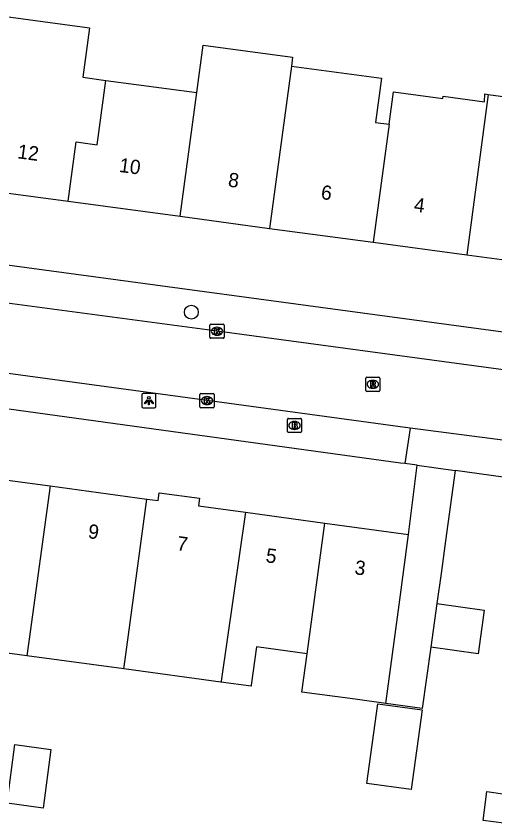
# Model space of a CAD drawing. Extents: x 161258 to 161838, y 380836 to 381727.
# Drawn here: x 161670.2 to 161703.9, y 381549.8 to 381606.5 of the extents above; entities that cross this region are included whole.
import ezdxf

# ---------------------------------------------------------------- set-up
doc = ezdxf.new("R2010")
doc.units = 0
for name, color, linetype in [('IMGEO_Boom', 7, 'Continuous'), ('IMGEO_Brandkraan', 7, 'Continuous'), ('IMGEO_Kolk', 7, 'Continuous'), ('IMGEO_Lichtpunt', 7, 'Continuous'), ('IMGEO_Pand', 7, 'Continuous'), ('IMGEO_Pand_nummerreeks', 7, 'Continuous'), ('IMGEO_Rijbaan_lokaal_open', 7, 'Continuous'), ('IMGEO_Rioolput', 7, 'Continuous'), ('IMGEO_Voetpad_open', 7, 'Continuous')]:
    doc.layers.add(name, color=color, linetype=linetype)

msp = doc.modelspace()

# ---------------------------------------------------------------- linework, layer by layer
at = {"layer": 'IMGEO_Boom'}
msp.add_circle((161682.565, 381585.699), 0.489, dxfattribs=at)
at = {"layer": 'IMGEO_Brandkraan'}
for p, q in [((161689.314, 381577.311), (161689.314, 381578.163)), ((161689.389, 381578.237), (161690.241, 381578.237)), ((161690.315, 381578.163), (161690.315, 381577.311)), ((161689.825, 381577.457), (161689.8, 381577.457)), ((161689.802, 381578.017), (161689.827, 381578.017)), ((161690.241, 381577.237), (161689.389, 381577.237))]:
    msp.add_line(p, q, dxfattribs=at)
for points in [[(161689.314, 381577.311), (161689.314, 381578.163)], [(161689.389, 381578.237), (161690.241, 381578.237)], [(161690.315, 381578.163), (161690.315, 381577.311)], [(161689.662, 381577.937), (161689.662, 381577.537), (161689.875, 381577.537)], [(161689.893, 381577.937), (161689.662, 381577.937)], [(161689.841, 381577.856), (161689.787, 381577.856), (161689.787, 381577.78)], [(161689.787, 381577.78), (161689.84, 381577.78)], [(161689.849, 381577.704), (161689.787, 381577.704), (161689.787, 381577.623)], [(161689.787, 381577.623), (161689.849, 381577.623)], [(161690.241, 381577.237), (161689.389, 381577.237)]]:
    msp.add_lwpolyline(points, dxfattribs=at)
for centre, radius, start, end in [((161689.391, 381578.161), 0.0765, 91.552, 178.448), ((161689.391, 381578.161), 0.0765, 91.552, 178.448), ((161690.239, 381578.161), 0.0765, 1.552, 88.448), ((161690.239, 381578.161), 0.0765, 1.552, 88.448), ((161689.842, 381577.818), 0.0379, 267.8285, 90.9355), ((161689.85, 381577.663), 0.0404, 269.8759, 90.5077), ((161689.881, 381577.788), 0.251, 268.6676, 293.5347), ((161689.897, 381577.792), 0.145, 59.4692, 91.5367), ((161689.922, 381577.839), 0.0922, 285.5137, 58.1501), ((161689.927, 381577.647), 0.105, 301.3115, 78.989), ((161689.391, 381577.313), 0.0765, 181.552, 268.448), ((161689.391, 381577.313), 0.0765, 181.552, 268.448), ((161690.239, 381577.313), 0.0765, 271.552, 358.448), ((161690.239, 381577.313), 0.0765, 271.552, 358.448)]:
    msp.add_arc(centre, radius, start, end, dxfattribs=at)
for centre, major_axis, ratio, start_param, end_param in [((161689.801, 381577.737), (-0.387, 0.002), 0.722429, 4.712389, 7.853982), ((161689.826, 381577.737), (-0.39, 0.002), 0.717154, 1.570796, 4.712389)]:
    msp.add_ellipse(centre, major_axis=major_axis, ratio=ratio, start_param=start_param, end_param=end_param, dxfattribs=at)
at = {"layer": 'IMGEO_Kolk'}
for p, q in [((161683.942, 381584.859), (161684.794, 381584.859)), ((161683.867, 381583.933), (161683.867, 381584.785)), ((161684.355, 381584.639), (161684.38, 381584.639)), ((161684.868, 381584.785), (161684.868, 381583.933)), ((161684.794, 381583.859), (161683.942, 381583.859)), ((161684.378, 381584.079), (161684.353, 381584.079)), ((161683.164, 381579.056), (161683.164, 381579.908)), ((161683.239, 381579.982), (161684.091, 381579.982)), ((161683.652, 381579.762), (161683.677, 381579.762)), ((161684.165, 381579.908), (161684.165, 381579.056)), ((161683.675, 381579.202), (161683.65, 381579.202)), ((161684.091, 381578.982), (161683.239, 381578.982))]:
    msp.add_line(p, q, dxfattribs=at)
for points in [[(161683.942, 381584.859), (161684.794, 381584.859)], [(161683.867, 381583.933), (161683.867, 381584.785)], [(161684.188, 381584.559), (161684.311, 381584.559), (161684.311, 381584.408), (161684.441, 381584.559), (161684.605, 381584.559), (161684.459, 381584.408), (161684.612, 381584.159), (161684.46, 381584.159), (161684.375, 381584.323), (161684.311, 381584.256), (161684.311, 381584.159), (161684.188, 381584.159), (161684.188, 381584.559)], [(161684.868, 381584.785), (161684.868, 381583.933)], [(161684.794, 381583.859), (161683.942, 381583.859)], [(161683.164, 381579.056), (161683.164, 381579.908)], [(161683.239, 381579.982), (161684.091, 381579.982)], [(161684.165, 381579.908), (161684.165, 381579.056)], [(161683.485, 381579.682), (161683.608, 381579.682), (161683.608, 381579.531), (161683.738, 381579.682), (161683.902, 381579.682), (161683.756, 381579.531), (161683.909, 381579.282), (161683.757, 381579.282), (161683.672, 381579.446), (161683.608, 381579.379), (161683.608, 381579.282), (161683.485, 381579.282), (161683.485, 381579.682)], [(161684.091, 381578.982), (161683.239, 381578.982)]]:
    msp.add_lwpolyline(points, dxfattribs=at)
for centre, start, end in [((161683.944, 381584.783), 91.552, 178.448), ((161683.944, 381584.783), 91.552, 178.448), ((161684.792, 381584.783), 1.552, 88.448), ((161684.792, 381584.783), 1.552, 88.448), ((161683.944, 381583.935), 181.552, 268.448), ((161683.944, 381583.935), 181.552, 268.448), ((161684.792, 381583.935), 271.552, 358.448), ((161684.792, 381583.935), 271.552, 358.448), ((161683.241, 381579.906), 91.552, 178.448), ((161683.241, 381579.906), 91.552, 178.448), ((161684.089, 381579.906), 1.552, 88.448), ((161684.089, 381579.906), 1.552, 88.448), ((161683.241, 381579.058), 181.552, 268.448), ((161683.241, 381579.058), 181.552, 268.448), ((161684.089, 381579.058), 271.552, 358.448), ((161684.089, 381579.058), 271.552, 358.448)]:
    msp.add_arc(centre, 0.0765, start, end, dxfattribs=at)
for centre, major_axis, ratio, start_param, end_param in [((161684.354, 381584.359), (-0.387, 0.002), 0.722429, 4.712389, 7.853982), ((161684.379, 381584.359), (-0.39, 0.002), 0.717154, 1.570796, 4.712389), ((161683.651, 381579.482), (-0.387, 0.002), 0.722429, 4.712389, 7.853982), ((161683.676, 381579.482), (-0.39, 0.002), 0.717154, 1.570796, 4.712389)]:
    msp.add_ellipse(centre, major_axis=major_axis, ratio=ratio, start_param=start_param, end_param=end_param, dxfattribs=at)
at = {"layer": 'IMGEO_Lichtpunt'}
for p, q in [((161679.082, 381579.883), (161679.082, 381579.076)), ((161679.082, 381579.883), (161679.082, 381579.076)), ((161679.984, 381579.978), (161679.176, 381579.978)), ((161679.984, 381579.978), (161679.176, 381579.978)), ((161680.078, 381579.076), (161680.078, 381579.883)), ((161680.078, 381579.076), (161680.078, 381579.883)), ((161679.176, 381578.982), (161679.984, 381578.982)), ((161679.176, 381578.982), (161679.984, 381578.982))]:
    msp.add_line(p, q, dxfattribs=at)
for points in [[(161679.456, 381579.547), (161679.495, 381579.519), (161679.307, 381579.257), (161679.269, 381579.284), (161679.456, 381579.547)], [(161679.558, 381579.499), (161679.605, 381579.499), (161679.605, 381579.177), (161679.558, 381579.177), (161679.558, 381579.499)], [(161679.668, 381579.519), (161679.706, 381579.546), (161679.893, 381579.284), (161679.854, 381579.256), (161679.668, 381579.519)]]:
    msp.add_lwpolyline(points, dxfattribs=at)
msp.add_circle((161679.581, 381579.681), 0.0994, dxfattribs=at)
for centre, start, end in [((161679.176, 381579.883), 90, 180), ((161679.176, 381579.883), 90, 180), ((161679.984, 381579.883), 0, 90), ((161679.984, 381579.883), 0, 90), ((161679.176, 381579.076), 180, 270), ((161679.176, 381579.076), 180, 270), ((161679.984, 381579.076), 270, 0), ((161679.984, 381579.076), 270, 360)]:
    msp.add_arc(centre, 0.0946, start, end, dxfattribs=at)
at = {"layer": 'IMGEO_Pand'}
for points in [[(161668.903, 381603.01), (161669.293, 381605.911), (161669.371, 381606.495), (161675.411, 381605.684), (161674.943, 381602.199), (161676.556, 381601.982)], [(161682.941, 381601.124), (161683.39, 381604.465), (161689.683, 381603.619), (161689.598, 381602.986)], [(161689.598, 381602.986), (161688.066, 381591.586)], [(161689.598, 381602.986), (161695.932, 381602.136), (161695.514, 381599.03), (161696.469, 381598.902)], [(161703.436, 381600.996), (161706.372, 381600.589), (161706.655, 381602.516), (161711.19, 381602.051)], [(161673.908, 381593.488), (161674.468, 381597.658), (161675.948, 381597.459), (161676.556, 381601.982)], [(161676.556, 381601.982), (161682.941, 381601.124)], [(161681.773, 381592.431), (161682.941, 381601.124)], [(161696.469, 381598.902), (161696.775, 381601.179), (161700.243, 381600.713), (161700.264, 381600.871), (161703.168, 381600.481), (161703.187, 381601.031), (161703.436, 381600.996)], [(161703.436, 381600.996), (161701.922, 381589.725)], [(161696.469, 381598.902), (161695.354, 381590.607)], [(161667.735, 381594.317), (161673.908, 381593.488)], [(161673.908, 381593.488), (161681.773, 381592.431)], [(161681.773, 381592.431), (161688.066, 381591.586)], [(161688.066, 381591.586), (161695.354, 381590.607)], [(161701.922, 381589.725), (161707.903, 381588.922), (161708.256, 381591.548), (161709.752, 381591.347)], [(161695.354, 381590.607), (161701.922, 381589.725)], [(161666.71, 381574.256), (161667.111, 381574.202), (161667.779, 381574.711), (161669.169, 381574.522), (161669.65, 381573.891), (161672.64, 381573.485)], [(161672.64, 381573.485), (161671.156, 381562.73), (161671.088, 381562.229), (161670.994, 381561.555)], [(161672.64, 381573.485), (161679.446, 381572.562)], [(161679.446, 381572.562), (161680.224, 381572.456), (161680.298, 381573.003), (161683.135, 381572.618), (161683.063, 381572.087), (161686.368, 381571.638)], [(161677.829, 381560.628), (161677.92, 381561.301), (161679.446, 381572.562)], [(161686.368, 381571.638), (161684.653, 381559.783), (161684.642, 381559.704)], [(161686.368, 381571.638), (161691.942, 381570.882)], [(161690.699, 381561.704), (161691.942, 381570.882)], [(161691.942, 381570.882), (161697.835, 381570.082)], [(161696.223, 381558.208), (161697.162, 381565.128), (161697.835, 381570.082)], [(161699.82, 381565.219), (161703.146, 381564.757), (161702.721, 381561.697), (161699.395, 381562.159)], [(161699.82, 381565.219), (161699.395, 381562.159)], [(161670.994, 381561.555), (161664.925, 381562.378)], [(161690.699, 381561.704), (161687.141, 381562.187), (161686.775, 381559.495), (161686.764, 381559.416), (161684.642, 381559.704)], [(161696.223, 381558.208), (161694.067, 381558.5), (161690.334, 381559.006), (161690.699, 381561.704)], [(161677.829, 381560.628), (161670.994, 381561.555)], [(161684.642, 381559.704), (161677.829, 381560.628)], [(161694.907, 381552.582), (161695.668, 381558.188), (161698.782, 381557.766), (161698.021, 381552.161), (161694.907, 381552.582)], [(161672.15, 381550.861), (161669.619, 381551.2), (161670.169, 381555.312), (161672.7, 381554.974), (161672.15, 381550.861)], [(161703.07, 381549.987), (161703.344, 381552.016), (161706.247, 381551.591), (161705.978, 381549.6), (161703.07, 381549.987)]]:
    msp.add_lwpolyline(points, dxfattribs=at)
at = {"layer": 'IMGEO_Rijbaan_lokaal_open'}
for points in [[(161707.156, 381581.295), (161706.756, 381581.348), (161684.368, 381584.359), (161663.266, 381587.166), (161645.071, 381589.627), (161619.675, 381593.074), (161618.458, 381593.224), (161618.426, 381593.228), (161614.689, 381593.717), (161591.61, 381596.833), (161591.3, 381596.865), (161590.603, 381596.979), (161590.506, 381597.003), (161590.41, 381597.026)], [(161697.936, 381577.548), (161697.62, 381577.589), (161697.6, 381577.592), (161683.665, 381579.482), (161662.594, 381582.337), (161656.447, 381583.147), (161646.629, 381584.448), (161644.429, 381584.771), (161619.122, 381588.157), (161617.916, 381588.319), (161614.153, 381588.812), (161591.008, 381591.931), (161589.798, 381592.101), (161589.764, 381592.108), (161589.729, 381592.114)], [(161704.805, 381576.659), (161697.936, 381577.548)]]:
    msp.add_lwpolyline(points, dxfattribs=at)
at = {"layer": 'IMGEO_Rioolput'}
for p, q in [((161694.819, 381580.202), (161694.819, 381581.054)), ((161694.894, 381581.128), (161695.746, 381581.128)), ((161695.307, 381580.908), (161695.332, 381580.908)), ((161695.82, 381581.054), (161695.82, 381580.202)), ((161695.33, 381580.348), (161695.305, 381580.348)), ((161695.746, 381580.128), (161694.894, 381580.128))]:
    msp.add_line(p, q, dxfattribs=at)
for points in [[(161694.819, 381580.202), (161694.819, 381581.054)], [(161694.894, 381581.128), (161695.746, 381581.128)], [(161695.82, 381581.054), (161695.82, 381580.202)], [(161695.408, 381580.826), (161695.156, 381580.828), (161695.156, 381580.428)], [(161695.156, 381580.428), (161695.28, 381580.428), (161695.28, 381580.59), (161695.291, 381580.59)], [(161695.334, 381580.747), (161695.28, 381580.747), (161695.28, 381580.666)], [(161695.28, 381580.666), (161695.332, 381580.666)], [(161695.338, 381580.561), (161695.409, 381580.428), (161695.549, 381580.428), (161695.484, 381580.554)], [(161695.746, 381580.128), (161694.894, 381580.128)]]:
    msp.add_lwpolyline(points, dxfattribs=at)
for centre, radius, start, end in [((161694.896, 381581.052), 0.0765, 91.552, 178.448), ((161694.896, 381581.052), 0.0765, 91.552, 178.448), ((161695.744, 381581.052), 0.0765, 1.552, 88.448), ((161695.744, 381581.052), 0.0765, 1.552, 88.448), ((161695.29, 381580.537), 0.0533, 26.0293, 88.6989), ((161695.316, 381580.855), 0.19, 274.7715, 282.9687), ((161695.34, 381580.651), 0.0964, 77.0061, 93.1865), ((161695.354, 381580.708), 0.0378, 276.6634, 79.6772), ((161695.407, 381580.716), 0.109, 350.3612, 89.416), ((161695.405, 381580.716), 0.112, 277.5842, 350.9817), ((161695.389, 381580.501), 0.108, 29.5134, 73.7905), ((161694.896, 381580.204), 0.0765, 181.552, 268.448), ((161694.896, 381580.204), 0.0765, 181.552, 268.448), ((161695.744, 381580.204), 0.0765, 271.552, 358.448), ((161695.744, 381580.204), 0.0765, 271.552, 358.448)]:
    msp.add_arc(centre, radius, start, end, dxfattribs=at)
for centre, major_axis, ratio, start_param, end_param in [((161695.306, 381580.628), (-0.387, 0.002), 0.722429, 4.712389, 7.853982), ((161695.331, 381580.628), (-0.39, 0.002), 0.717154, 1.570796, 4.712389)]:
    msp.add_ellipse(centre, major_axis=major_axis, ratio=ratio, start_param=start_param, end_param=end_param, dxfattribs=at)
at = {"layer": 'IMGEO_Voetpad_open'}
for points in [[(161707.511, 381583.893), (161707.085, 381583.95), (161615.118, 381596.359)], [(161697.567, 381575.055), (161697.263, 381575.097), (161654.253, 381581.004), (161654.227, 381580.806)], [(161697.936, 381577.548), (161697.567, 381575.055)], [(161698.43, 381574.937), (161697.567, 381575.055)], [(161697.835, 381570.082), (161698.43, 381574.937)], [(161698.43, 381574.937), (161701.111, 381574.569)], [(161701.111, 381574.569), (161700.434, 381569.637), (161700.115, 381567.341), (161699.82, 381565.219)], [(161704.491, 381574.105), (161701.111, 381574.569)], [(161699.395, 381562.159), (161698.798, 381557.859), (161696.223, 381558.208)]]:
    msp.add_lwpolyline(points, dxfattribs=at)

# ---------------------------------------------------------------- texts
at = {"layer": 'IMGEO_Pand_nummerreeks'}
for s, rotation, p in [('12', 352.351, (161670.3, 381596.514)), ('10', 352.3507, (161677.449, 381595.555)), ('8', 352.3507, (161685.106, 381594.527)), ('6', 352.3507, (161691.635, 381593.65)), ('4', 352.351, (161698.167, 381592.772)), ('9', 352.288, (161675.262, 381569.829)), ('7', 352.288, (161681.508, 381568.983)), ('5', 352.288, (161687.753, 381568.137)), ('3', 352.2859, (161693.999, 381567.292))]:
    msp.add_text(s, height=1, rotation=rotation, dxfattribs=at).set_placement(p)

doc.saveas('drawing.dxf')
